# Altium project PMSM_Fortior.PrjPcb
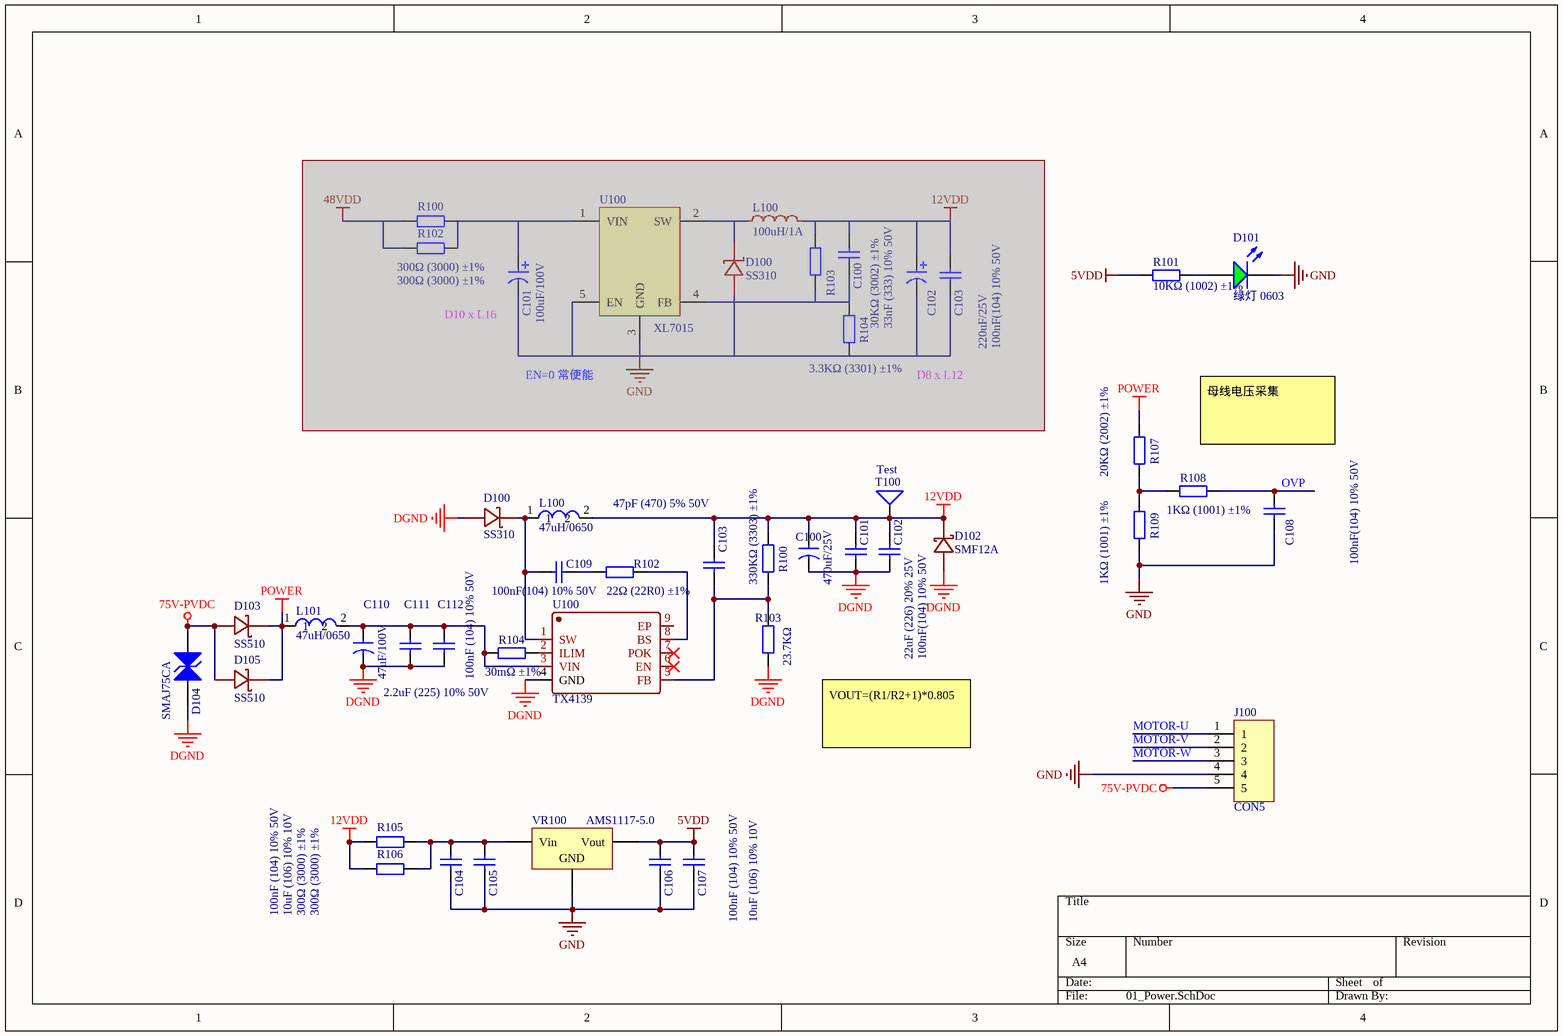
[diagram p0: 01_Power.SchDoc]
4 sheets, 140 parts. Net scope: global (net labels, ports and power ports of the same name join across sheets).
Sheets:
  01_Power.SchDoc
  02_MCU.SchDoc
  03_Mos.SchDoc
  04_Sensor.SchDoc

## Sheet 01_Power.SchDoc
size A4

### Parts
(Parts that share a designator on the sheet are numbered #1, #2 ... from top to bottom, then left to right.)
C100#1  33nF (333) 10% 50V  [0603_C]  (masked out: inside a compile mask, not in the netlist)
C100#2  470uF/25V  [47UF/100V]
C101#1  100uF/100V  [CAP_D10_L16]  (masked out: inside a compile mask, not in the netlist)
C101#2  22uF (226) 20% 25V  [0805_C]
C102#1  220uF/25V  [CAP_D8_L12]  (masked out: inside a compile mask, not in the netlist)
C102#2  100nF(104) 10% 50V  [0805_C]
C103#1  100nF(104) 10% 50V  [0805_C]  (masked out: inside a compile mask, not in the netlist)
C103#2  47pF (470) 5% 50V  [0805_C]
C104  100nF (104) 10% 50V  [0603_C]
C105  10uF (106) 10% 10V  [0603_C]
C106  100nF (104) 10% 50V  [0603_C]
C107  10uF (106) 10% 10V  [0603_C]
C108  100nF(104) 10% 50V  [0805_C]
C109  100nF(104) 10% 50V  [0805_C]
C110  47uF/100V  [47UF/100V]
C111  2.2uF (225) 10% 50V  [1206_C]
C112  100nF (104) 10% 50V  [1206_C]
D100#1  SS310  [SS310]  (masked out: inside a compile mask, not in the netlist)
D100#2  SS310  [SS310]
D101  绿灯 0603  [0603_LED_S1]
D102  SMF12A  [SMF12A - duplicate]
D103  SS510  [SS510]
D104  SMAJ75CA  [SMB(DO-214AA)_S1]
D105  SS510  [SS510]
J100  CON5  [7.62-5P 端子]
L100#1  100uH/1A  [L_D9.5_L12]  (masked out: inside a compile mask, not in the netlist)
L100#2  47uH/0650  [0650_47uH]
L101  47uH/0650  [0650_47uH]
R100#1  300Ω (3000) ±1%  [1206_R]  (masked out: inside a compile mask, not in the netlist)
R100#2  330KΩ (3303) ±1%  [0805_R]
R101  10KΩ (1002) ±1%  [0603_R]
R102#1  300Ω (3000) ±1%  [1206_R]  (masked out: inside a compile mask, not in the netlist)
R102#2  22Ω (22R0) ±1%  [0805_R]
R103#1  30KΩ (3002) ±1%  [0603_R]  (masked out: inside a compile mask, not in the netlist)
R103#2  23.7KΩ  [0805_R]
R104#1  3.3KΩ (3301) ±1%  [0603_R]  (masked out: inside a compile mask, not in the netlist)
R104#2  30mΩ ±1%  [LC-0603_R]
R105  300Ω (3000) ±1%  [1206_R]
R106  300Ω (3000) ±1%  [1206_R]
R107  20KΩ (2002) ±1%  [0805_R]
R108  1KΩ (1001) ±1%  [0805_R]
R109  1KΩ (1001) ±1%  [0805_R]
T100  Test  [Testpoint]
U100#1  XL7015  [XL7015]  (masked out: inside a compile mask, not in the netlist)
U100#2  TX4139  [ESOP8]
VR100  AMS1117-5.0  [SOT-223]

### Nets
5VDD: C106.2 C107.2 R101.2 VR100.2(Vout)
12VDD: C100#2.1 C101#2.2 C102#2.2 C103#2.2 D102.1(K) L100#2.2 R100#2.2 R105.1 R106.1 T100.1
75V-PVDC: D103.2 D104.1(A) D105.2 J100.5
DGND: C100#2.2 C101#2.1 C102#2.1 C110.2 C111.1 C112.1 D100#2.2(A) D102.2(A) D104.2(K) R103#2.1 U100#2.4(GND)
GND: C104.1 C105.1 C106.1 C107.1 C108.1 D101.K J100.4 R109.1 VR100.1(GND)
POWER: D103.1 D105.1 L101.1 R107.2
MOTOR-U: J100.1
MOTOR-V: J100.2
MOTOR-W: J100.3
OVP: C108.2 R108.1
NetC103#2_1: C103#2.1 R100#2.1 R103#2.2 U100#2.5(FB)
NetC104_2: C104.2 C105.2 R105.2 R106.2 VR100.3(Vin)
NetC109_1: C109.1 D100#2.1(K) L100#2.1 U100#2.1(SW)
NetC109_2: C109.2 R102#2.1
NetC110_1: C110.1 C111.2 C112.2 L101.2 R104#2.2 U100#2.3(VIN)
NetD101_A: D101.A R101.1
NetR102#2_2: R102#2.2 U100#2.8(BS)
NetR104#2_1: R104#2.1 U100#2.2(ILIM)
NetR107_1: R107.1 R108.2 R109.2

Not connected (* = marked no-connect by the designer): U100#2 6(EN)* 7(POK)* 9(EP)

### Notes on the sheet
- (near C101#1) D10 x L16
- EN=0 常使能
- D8 x L12
- 母线电压采集
- VOUT=(R1/R2+1)*0.805

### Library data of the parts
C100#1 = 0603 33nF (333) 10% 50V: 贴片电容
C100#2 C110 = CapSMT220u_16V
C101#1 C102#1 = CAP2: 电解电容
C101#2 = 0805 22uF (226) 20% 25V: 贴片电容
C102#2 C103#1 C108 C109 = 0805 100nF(104) 10% 50V: 贴片电容
C103#2 = 0805 47pF (470) 5% 50V: 贴片电容
C104 C106 = 0603 100nF (104) 10% 50V: 贴片电容
C105 C107 = 0603 10uF (106) 10% 10V: 贴片电容
C111 = 1206 2.2uF (225) 10% 50V: 贴片电容
C112 = 1206 100nF (104) 10% 50V: 贴片电容
D101 = 0603 绿灯: 发光二极管
D104 = SMB/DO-214AA P6SMB6.8CA: TVS
L100#1 = L
L100#2 L101 = Inductor
R100#1 R102#1 R105 R106 = 1206 300Ω (3000) 1%: 贴片电阻
R100#2 = 0805 330KΩ (3303) 1%: 贴片电阻
R101 = 0603 10KΩ (1002) 1%: 贴片电阻
R102#2 R103#2 = 0805 22Ω (22R0) 1%: 贴片电阻
R103#1 = 0603 30KΩ (3002) 1%: 贴片电阻
R104#1 = 0603 3.3KΩ (3301) 1%: 贴片电阻
R104#2 = 0603 100KΩ (1003) 1%: 贴片电阻
R107 = 0805 20KΩ (2002) 1%: 贴片电阻
R108 R109 = 0805 1KΩ (1001) 1%: 贴片电阻
T100 = TestPad
VR100 = SOT-223 AMS1117-5.0: 低压差线性稳压(LDO)

## Sheet 02_MCU.SchDoc
size A4
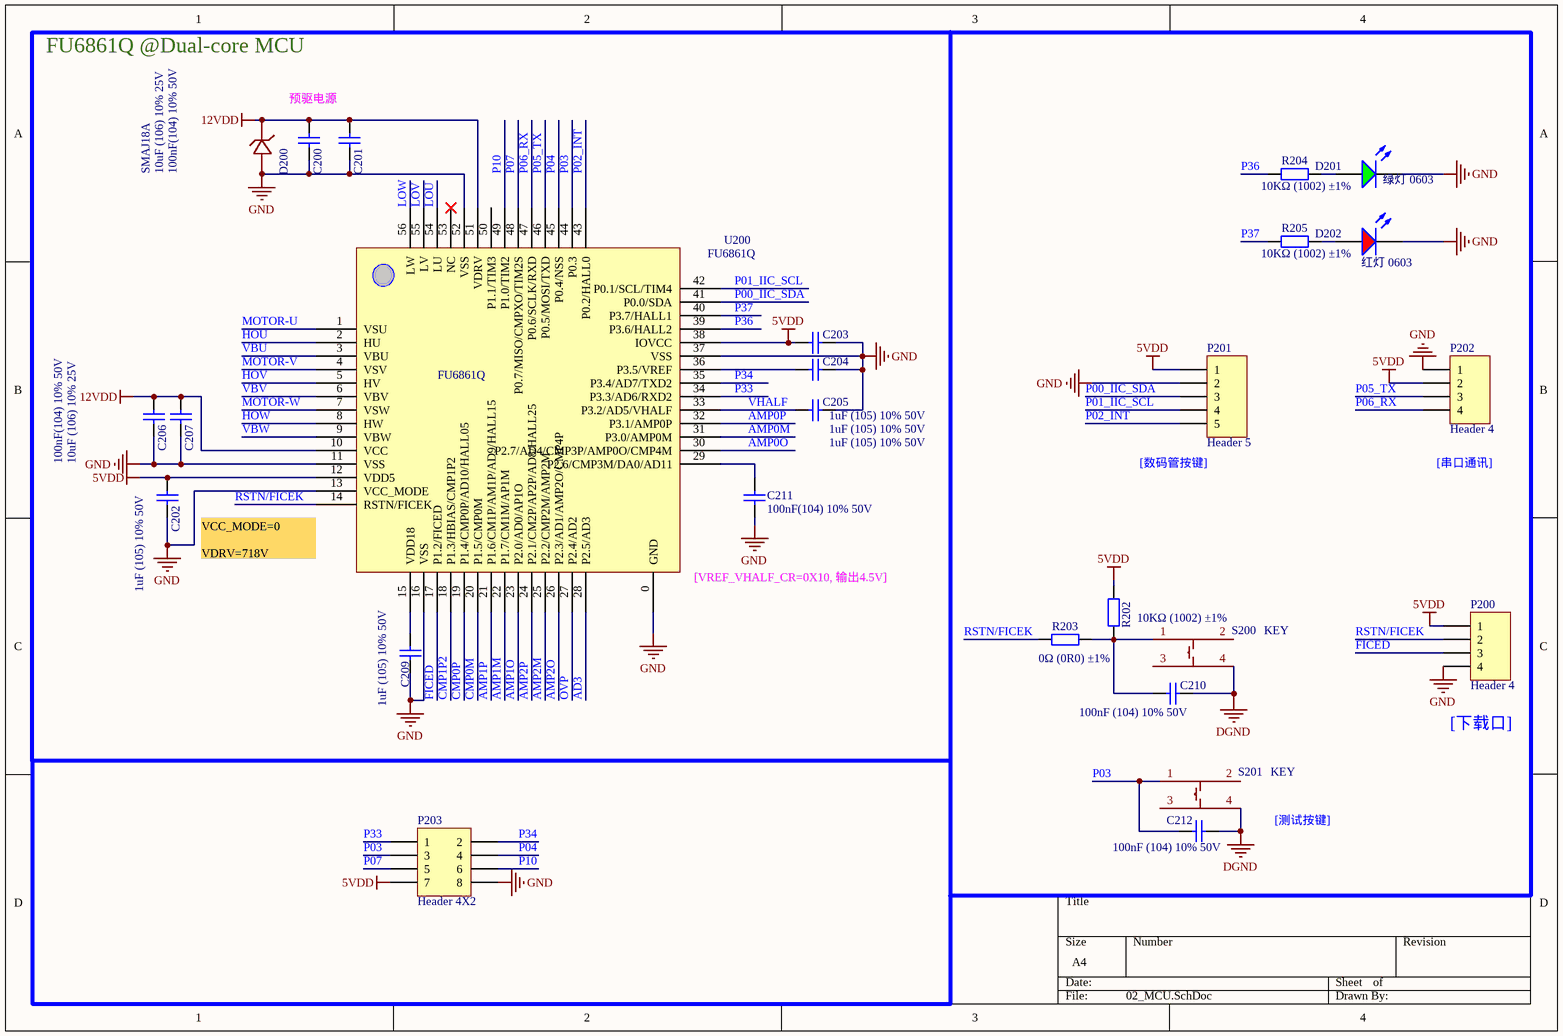
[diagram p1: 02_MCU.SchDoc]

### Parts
C200  10uF (106) 10% 25V  [0805_C]
C201  100nF(104) 10% 50V  [0805_C]
C202  1uF (105) 10% 50V  [0805_C]
C203  1uF (105) 10% 50V  [0805_C]
C204  1uF (105) 10% 50V  [0805_C]
C205  1uF (105) 10% 50V  [0805_C]
C206  10uF (106) 10% 25V  [0805_C]
C207  100nF(104) 10% 50V  [0805_C]
C209  1uF (105) 10% 50V  [0805_C]
C210  100nF (104) 10% 50V  [0603_C]
C211  100nF(104) 10% 50V  [0805_C]
C212  100nF (104) 10% 50V  [0603_C]
D200  SMAJ18A  [SMAJ18A]
D201  绿灯 0603  [0603_LED_S1]
D202  红灯 0603  [0603_LED_S1]
P200  Header 4  [HDR1X4]
P201  Header 5  [HDR1X5]
P202  Header 4  [HDR1X4]
P203  Header 4X2  [HDR2X4]
R202  10KΩ (1002) ±1%  [0603_R]
R203  0Ω (0R0) ±1%  [0603_R]
R204  10KΩ (1002) ±1%  [0805_R]
R205  10KΩ (1002) ±1%  [0805_R]
S200  KEY  [KEY_WHITE]
S201  KEY  [KEY_WHITE]
U200  FU6861Q  [FU6861Q]

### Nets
5VDD: C202.2 C203.1 P200.1 P201.1 P202.2 P203.7 R202.2 U200.12(VDD5) U200.38(IOVCC)
12VDD: C200.2 C201.2 C206.2 C207.2 D200.1(C) U200.10(VCC) U200.51(VDRV)
DGND: C210.2 C212.1 S200.4 S201.4
GND: C200.1 C201.1 C202.1 C203.2 C204.2 C205.2 C206.1 C207.1 C209.1 C211.2 D200.2(A) D201.K D202.K P200.4 P201.2 P202.1 P203.8 U200.0(GND) U200.11(VSS) U200.13(VCC_MODE) U200.16(VSS) U200.37(VSS) U200.52(VSS)
AD3: U200.28(P2.5/AD3)
AMP0M: U200.31(P3.0/AMP0M)
AMP0O: U200.30(P2.7/AD4/CMP3P/AMP0O/CMP4M)
AMP0P: U200.32(P3.1/AMP0P)
AMP1M: U200.22(P1.7/CM1M/AP1M)
AMP1O: U200.23(P2.0/AD0/AP1O)
AMP1P: U200.21(P1.6/CM1P/AM1P/AD9/HALL15)
AMP2M: U200.25(P2.2/CMP2M/AMP2M)
AMP2O: U200.26(P2.3/AD1/AMP2O/CMP4P)
AMP2P: U200.24(P2.1/CM2P/AP2P/AD8/HALL25)
CMP0M: U200.20(P1.5/CMP0M)
CMP0P: U200.19(P1.4/CMP0P/AD10/HALL05)
CMP1P2: U200.18(P1.3/HBIAS/CMP1P2)
FICED: P200.3 U200.17(P1.2/FICED)
HOU: U200.2(HU)
HOV: U200.5(HV)
HOW: U200.8(HW)
LOU: U200.54(LU)
LOV: U200.55(LV)
LOW: U200.56(LW)
MOTOR-U: U200.1(VSU)
MOTOR-V: U200.4(VSV)
MOTOR-W: U200.7(VSW)
OVP: U200.27(P2.4/AD2)
P00_IIC_SDA: P201.3 U200.41(P0.0/SDA)
P01_IIC_SCL: P201.4 U200.42(P0.1/SCL/TIM4)
P02_INT: P201.5 U200.43(P0.2/HALL0)
P03: C212.2 P203.3 S201.1 U200.44(P0.3)
P04: P203.4 U200.45(P0.4/NSS)
P05_TX: P202.3 U200.46(P0.5/MOSI/TXD)
P06_RX: P202.4 U200.47(P0.6/SCLK/RXD)
P07: P203.5 U200.48(P0.7/MISO/CMPXO/TIM2S)
P10: P203.6 U200.49(P1.0/TIM2)
P33: P203.1 U200.34(P3.3/AD6/RXD2)
P34: P203.2 U200.35(P3.4/AD7/TXD2)
P36: R204.1 U200.39(P3.6/HALL2)
P37: R205.1 U200.40(P3.7/HALL1)
RSTN/FICEK: P200.2 R203.1 U200.14(RSTN/FICEK)
VBU: U200.3(VBU)
VBV: U200.6(VBV)
VBW: U200.9(VBW)
VHALF: C205.1 U200.33(P3.2/AD5/VHALF)
NetC204_1: C204.1 U200.36(P3.5/VREF)
NetC209_2: C209.2 U200.15(VDD18)
NetC210_1: C210.1 R202.1 R203.2 S200.1
NetC211_1: C211.1 U200.29(P2.6/CMP3M/DA0/AD11)
NetD201_A: D201.A R204.2
NetD202_A: D202.A R205.2

Not connected (* = marked no-connect by the designer): S200 2 3; S201 2 3; U200 50(P1.1/TIM3) 53(NC)*

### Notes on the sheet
- FU6861Q @Dual-core MCU
- 预驱电源
- (near P201) [数码管按键]
- (near P202) [串口通讯]
- VCC_MODE=0
  VDRV=718V
- (near U200) [VREF_VHALF_CR=0X10, 输出4.5V]
- (near P200) [下载口]
- [测试按键]

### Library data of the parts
C200 C206 = 0805 10uF (106) 10% 25V: 贴片电容
C201 C207 C211 = 0805 100nF(104) 10% 50V: 贴片电容
C202-C205 C209 = 0805 1uF (105) 10% 50V: 贴片电容
C210 C212 = 0603 100nF (104) 10% 50V: 贴片电容
D200 = SMAJ18A: C435545
D201 = 0603 绿灯: 发光二极管
D202 = 0603 红灯: 发光二极管
P200 P202 = Header 4: Header, 4-Pin
P201 = Header 5: Header, 5-Pin
P203 = Header 4X2: Header, 4-Pin, Dual row
R202 = 0603 10KΩ (1002) 1%: 贴片电阻
R203 = 0603 0Ω (0R0) 1%: 贴片电阻
R204 R205 = 0805 10KΩ (1002) 1%: 贴片电阻
S200 S201 = KEY: 白色方块

## Sheet 03_Mos.SchDoc
size A4
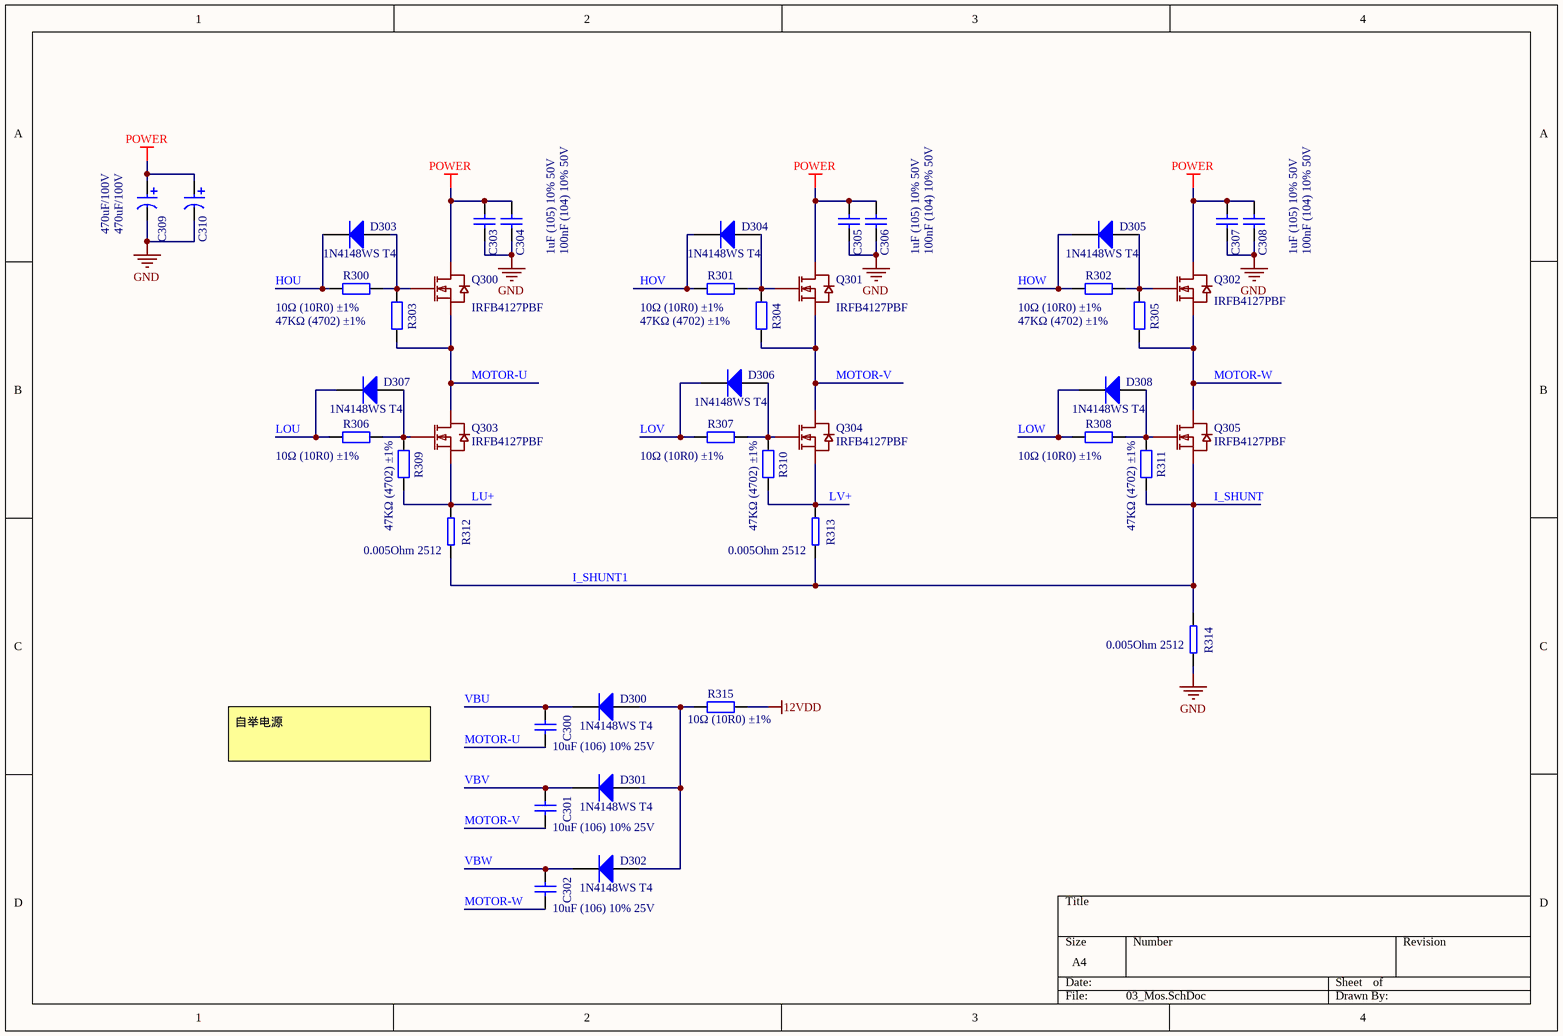
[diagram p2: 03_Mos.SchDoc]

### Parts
C300  10uF (106) 10% 25V  [0805_C]
C301  10uF (106) 10% 25V  [0805_C]
C302  10uF (106) 10% 25V  [0805_C]
C303  100nF (104) 10% 50V  [1206_C]
C304  1uF (105) 10% 50V  [1206_C]
C305  100nF (104) 10% 50V  [1206_C]
C306  1uF (105) 10% 50V  [1206_C]
C307  100nF (104) 10% 50V  [1206_C]
C308  1uF (105) 10% 50V  [1206_C]
C309  470uF/100V  [CAP_D16_L31.5]
C310  470uF/100V  [CAP_D16_L31.5]
D300  1N4148WS T4  [SOD-323]
D301  1N4148WS T4  [SOD-323]
D302  1N4148WS T4  [SOD-323]
D303  1N4148WS T4  [SOD-323]
D304  1N4148WS T4  [SOD-323]
D305  1N4148WS T4  [SOD-323]
D306  1N4148WS T4  [SOD-323]
D307  1N4148WS T4  [SOD-323]
D308  1N4148WS T4  [SOD-323]
Q300  IRFB4127PBF  [IRFB4127]
Q301  IRFB4127PBF  [IRFB4127]
Q302  IRFB4127PBF  [IRFB4127]
Q303  IRFB4127PBF  [IRFB4127]
Q304  IRFB4127PBF  [IRFB4127]
Q305  IRFB4127PBF  [IRFB4127]
R300  10Ω (10R0) ±1%  [0805_R]
R301  10Ω (10R0) ±1%  [0805_R]
R302  10Ω (10R0) ±1%  [0805_R]
R303  47KΩ (4702) ±1%  [0805_R]
R304  47KΩ (4702) ±1%  [0805_R]
R305  47KΩ (4702) ±1%  [0805_R]
R306  10Ω (10R0) ±1%  [0805_R]
R307  10Ω (10R0) ±1%  [0805_R]
R308  10Ω (10R0) ±1%  [0805_R]
R309  47KΩ (4702) ±1%  [0805_R]
R310  47KΩ (4702) ±1%  [0805_R]
R311  47KΩ (4702) ±1%  [0805_R]
R312  0.005Ohm 2512  [R2512]
R313  0.005Ohm 2512  [R2512]
R314  0.005Ohm 2512  [R2512]
R315  10Ω (10R0) ±1%  [0805_R]

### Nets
12VDD: R315.2
GND: C303.1 C304.1 C305.1 C306.1 C307.1 C308.1 C309.2 C310.2 R314.1
POWER: C303.2 C304.2 C305.2 C306.2 C307.2 C308.2 C309.1 C310.1 Q300.2(D) Q301.2(D) Q302.2(D)
HOU: D303.2(K) R300.1
HOV: D304.2(K) R301.1
HOW: D305.2(K) R302.1
I_SHUNT: Q305.3(S) R311.1 R312.1 R313.1 R314.2  [also labelled I_SHUNT1]
LOU: D307.2(K) R306.1
LOV: D306.2(K) R307.1
LOW: D308.2(K) R308.1
LU+: Q303.3(S) R309.1 R312.2
LV+: Q304.3(S) R310.1 R313.2
MOTOR-U: C300.1 Q300.3(S) Q303.2(D) R303.1
MOTOR-V: C301.1 Q301.3(S) Q304.2(D) R304.1
MOTOR-W: C302.1 Q302.3(S) Q305.2(D) R305.1
VBU: C300.2 D300.2(K)
VBV: C301.2 D301.2(K)
VBW: C302.2 D302.2(K)
NetD300_1: D300.1(A) D301.1(A) D302.1(A) R315.1
NetD303_1: D303.1(A) Q300.1(G) R300.2 R303.2
NetD304_1: D304.1(A) Q301.1(G) R301.2 R304.2
NetD305_1: D305.1(A) Q302.1(G) R302.2 R305.2
NetD306_1: D306.1(A) Q304.1(G) R307.2 R310.2
NetD307_1: D307.1(A) Q303.1(G) R306.2 R309.2
NetD308_1: D308.1(A) Q305.1(G) R308.2 R311.2

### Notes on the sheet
- 自举电源

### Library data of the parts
C300-C302 = 0805 10uF (106) 10% 25V: 贴片电容
C303 C305 C307 = 1206 100nF (104) 10% 50V: 贴片电容
C304 C306 C308 = 1206 1uF (105) 10% 50V: 贴片电容
C309 C310 = CAP2: 电解电容
D300-D308 = SOD-323 1N4148WS T4: 二极管
R300-R302 R306-R308 R315 = 0805 10Ω (10R0) 1%: 贴片电阻
R303-R305 R309-R311 = 0805 47KΩ (4702) 1%: 贴片电阻
R312-R314 = Res10K

## Sheet 04_Sensor.SchDoc
size A4
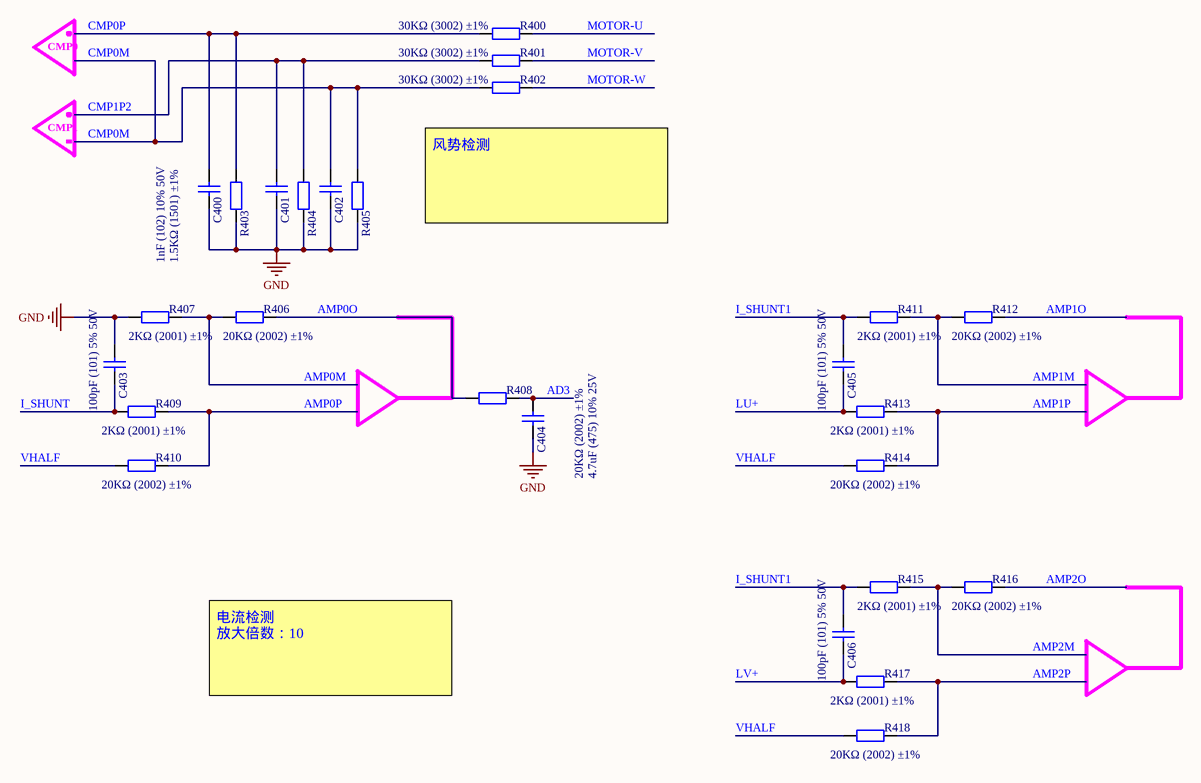
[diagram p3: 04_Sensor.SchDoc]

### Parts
C400  1nF (102) 10% 50V  [0805_C]
C401  1nF (102) 10% 50V  [0805_C]  (value not drawn)
C402  1nF (102) 10% 50V  [0805_C]  (value not drawn)
C403  100pF (101) 5% 50V  [0805_C]
C404  4.7uF (475) 10% 25V  [0805_C]
C405  100pF (101) 5% 50V  [0805_C]
C406  100pF (101) 5% 50V  [0805_C]
R400  30KΩ (3002) ±1%  [0805_R]
R401  30KΩ (3002) ±1%  [0805_R]
R402  30KΩ (3002) ±1%  [0805_R]
R403  1.5KΩ (1501) ±1%  [0805_R]
R404  1.5KΩ (1501) ±1%  [0805_R]  (value not drawn)
R405  1.5KΩ (1501) ±1%  [0805_R]  (value not drawn)
R406  20KΩ (2002) ±1%  [0805_R]
R407  2KΩ (2001) ±1%  [0805_R]
R408  20KΩ (2002) ±1%  [0805_R]
R409  2KΩ (2001) ±1%  [0805_R]
R410  20KΩ (2002) ±1%  [0805_R]
R411  2KΩ (2001) ±1%  [0805_R]
R412  20KΩ (2002) ±1%  [0805_R]
R413  2KΩ (2001) ±1%  [0805_R]
R414  20KΩ (2002) ±1%  [0805_R]
R415  2KΩ (2001) ±1%  [0805_R]
R416  20KΩ (2002) ±1%  [0805_R]
R417  2KΩ (2001) ±1%  [0805_R]
R418  20KΩ (2002) ±1%  [0805_R]

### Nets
GND: C400.1 C401.1 C402.1 C403.2 C404.1 R403.1 R404.1 R405.1 R407.1
AD3: C404.2 R408.2
AMP0M: R406.1 R407.2
AMP0O: R406.2 R408.1
AMP0P: R409.2 R410.2
AMP1M: R411.2 R412.1
AMP1O: R412.2
AMP1P: R413.2 R414.2
AMP2M: R415.2 R416.1
AMP2O: R416.2
AMP2P: R417.2 R418.2
CMP0M: C402.2 R402.1 R405.2
CMP0P: C400.2 R400.1 R403.2
CMP1P2: C401.2 R401.1 R404.2
I_SHUNT: C403.1 C405.2 C406.2 R409.1 R411.1 R415.1  [also labelled I_SHUNT1]
LU+: C405.1 R413.1
LV+: C406.1 R417.1
MOTOR-U: R400.2
MOTOR-V: R401.2
MOTOR-W: R402.2
VHALF: R410.1 R414.1 R418.1

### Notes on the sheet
- CMP0
- CMP1
- (near R402) 风势检测
- 电流检测
  放大倍数：10

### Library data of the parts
C400-C402 = 0805 1nF (102) 10% 50V: 贴片电容
C403 C405 C406 = 0805 100pF (101) 5% 50V: 贴片电容
C404 = 0805 4.7uF (475) 10% 25V: 贴片电容
R400-R402 = 0603 30KΩ (3002) 1%: 贴片电阻
R403-R405 = 0805 1.5KΩ (1501) 1%: 贴片电阻
R406 R408 R410 R412 R414 R416 R418 = 0805 20KΩ (2002) 1%: 贴片电阻
R407 R409 R411 R413 R415 R417 = 0805 2KΩ (2001) 1%: 贴片电阻

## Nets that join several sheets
5VDD: 01_Power (C106.2 C107.2 R101.2 VR100.2), 02_MCU (9 pins)
12VDD: 01_Power (10 pins), 02_MCU (7 pins), 03_Mos (R315.2)
DGND: 01_Power (11 pins), 02_MCU (C210.2 C212.1 S200.4 S201.4)
GND: 01_Power (9 pins), 02_MCU (23 pins), 03_Mos (9 pins), 04_Sensor (9 pins)
POWER: 01_Power (D103.1 D105.1 L101.1 R107.2), 03_Mos (11 pins)
AD3: 02_MCU (U200.28), 04_Sensor (C404.2 R408.2)
AMP0M: 02_MCU (U200.31), 04_Sensor (R406.1 R407.2)
AMP0O: 02_MCU (U200.30), 04_Sensor (R406.2 R408.1)
AMP0P: 02_MCU (U200.32), 04_Sensor (R409.2 R410.2)
AMP1M: 02_MCU (U200.22), 04_Sensor (R411.2 R412.1)
AMP1O: 02_MCU (U200.23), 04_Sensor (R412.2)
AMP1P: 02_MCU (U200.21), 04_Sensor (R413.2 R414.2)
AMP2M: 02_MCU (U200.25), 04_Sensor (R415.2 R416.1)
AMP2O: 02_MCU (U200.26), 04_Sensor (R416.2)
AMP2P: 02_MCU (U200.24), 04_Sensor (R417.2 R418.2)
CMP0M: 02_MCU (U200.20), 04_Sensor (C402.2 R402.1 R405.2)
CMP0P: 02_MCU (U200.19), 04_Sensor (C400.2 R400.1 R403.2)
CMP1P2: 02_MCU (U200.18), 04_Sensor (C401.2 R401.1 R404.2)
HOU: 02_MCU (U200.2), 03_Mos (D303.2 R300.1)
HOV: 02_MCU (U200.5), 03_Mos (D304.2 R301.1)
HOW: 02_MCU (U200.8), 03_Mos (D305.2 R302.1)
I_SHUNT: 03_Mos (5 pins), 04_Sensor (6 pins)
LOU: 02_MCU (U200.54), 03_Mos (D307.2 R306.1)
LOV: 02_MCU (U200.55), 03_Mos (D306.2 R307.1)
LOW: 02_MCU (U200.56), 03_Mos (D308.2 R308.1)
LU+: 03_Mos (Q303.3 R309.1 R312.2), 04_Sensor (C405.1 R413.1)
LV+: 03_Mos (Q304.3 R310.1 R313.2), 04_Sensor (C406.1 R417.1)
MOTOR-U: 01_Power (J100.1), 02_MCU (U200.1), 03_Mos (C300.1 Q300.3 Q303.2 R303.1), 04_Sensor (R400.2)
MOTOR-V: 01_Power (J100.2), 02_MCU (U200.4), 03_Mos (C301.1 Q301.3 Q304.2 R304.1), 04_Sensor (R401.2)
MOTOR-W: 01_Power (J100.3), 02_MCU (U200.7), 03_Mos (C302.1 Q302.3 Q305.2 R305.1), 04_Sensor (R402.2)
OVP: 01_Power (C108.2 R108.1), 02_MCU (U200.27)
VBU: 02_MCU (U200.3), 03_Mos (C300.2 D300.2)
VBV: 02_MCU (U200.6), 03_Mos (C301.2 D301.2)
VBW: 02_MCU (U200.9), 03_Mos (C302.2 D302.2)
VHALF: 02_MCU (C205.1 U200.33), 04_Sensor (R410.1 R414.1 R418.1)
